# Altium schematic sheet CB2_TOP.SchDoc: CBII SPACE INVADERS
size A2; Engineer: SHOWELL; DocumentNumber: 1; Revision: 1.00; SheetNumber: 1; SheetTotal: 1; PageSetup: Record=PageOptions|CenterHorizontal=True|CenterVertical=True|PrintScale=1.47|XCorrection=1.00|YCorrection=1.00|PrintKind=0|BorderSize=5000000|LeftOffset=0|BottomOffset=0|Orientation=2|PaperLength=1000|PaperWidth=1000|Scale=100|PaperSource=7|PrintQuality=-4|MediaType=1|DitherType=10|PaperKind=A2|PrintScaleMode=1
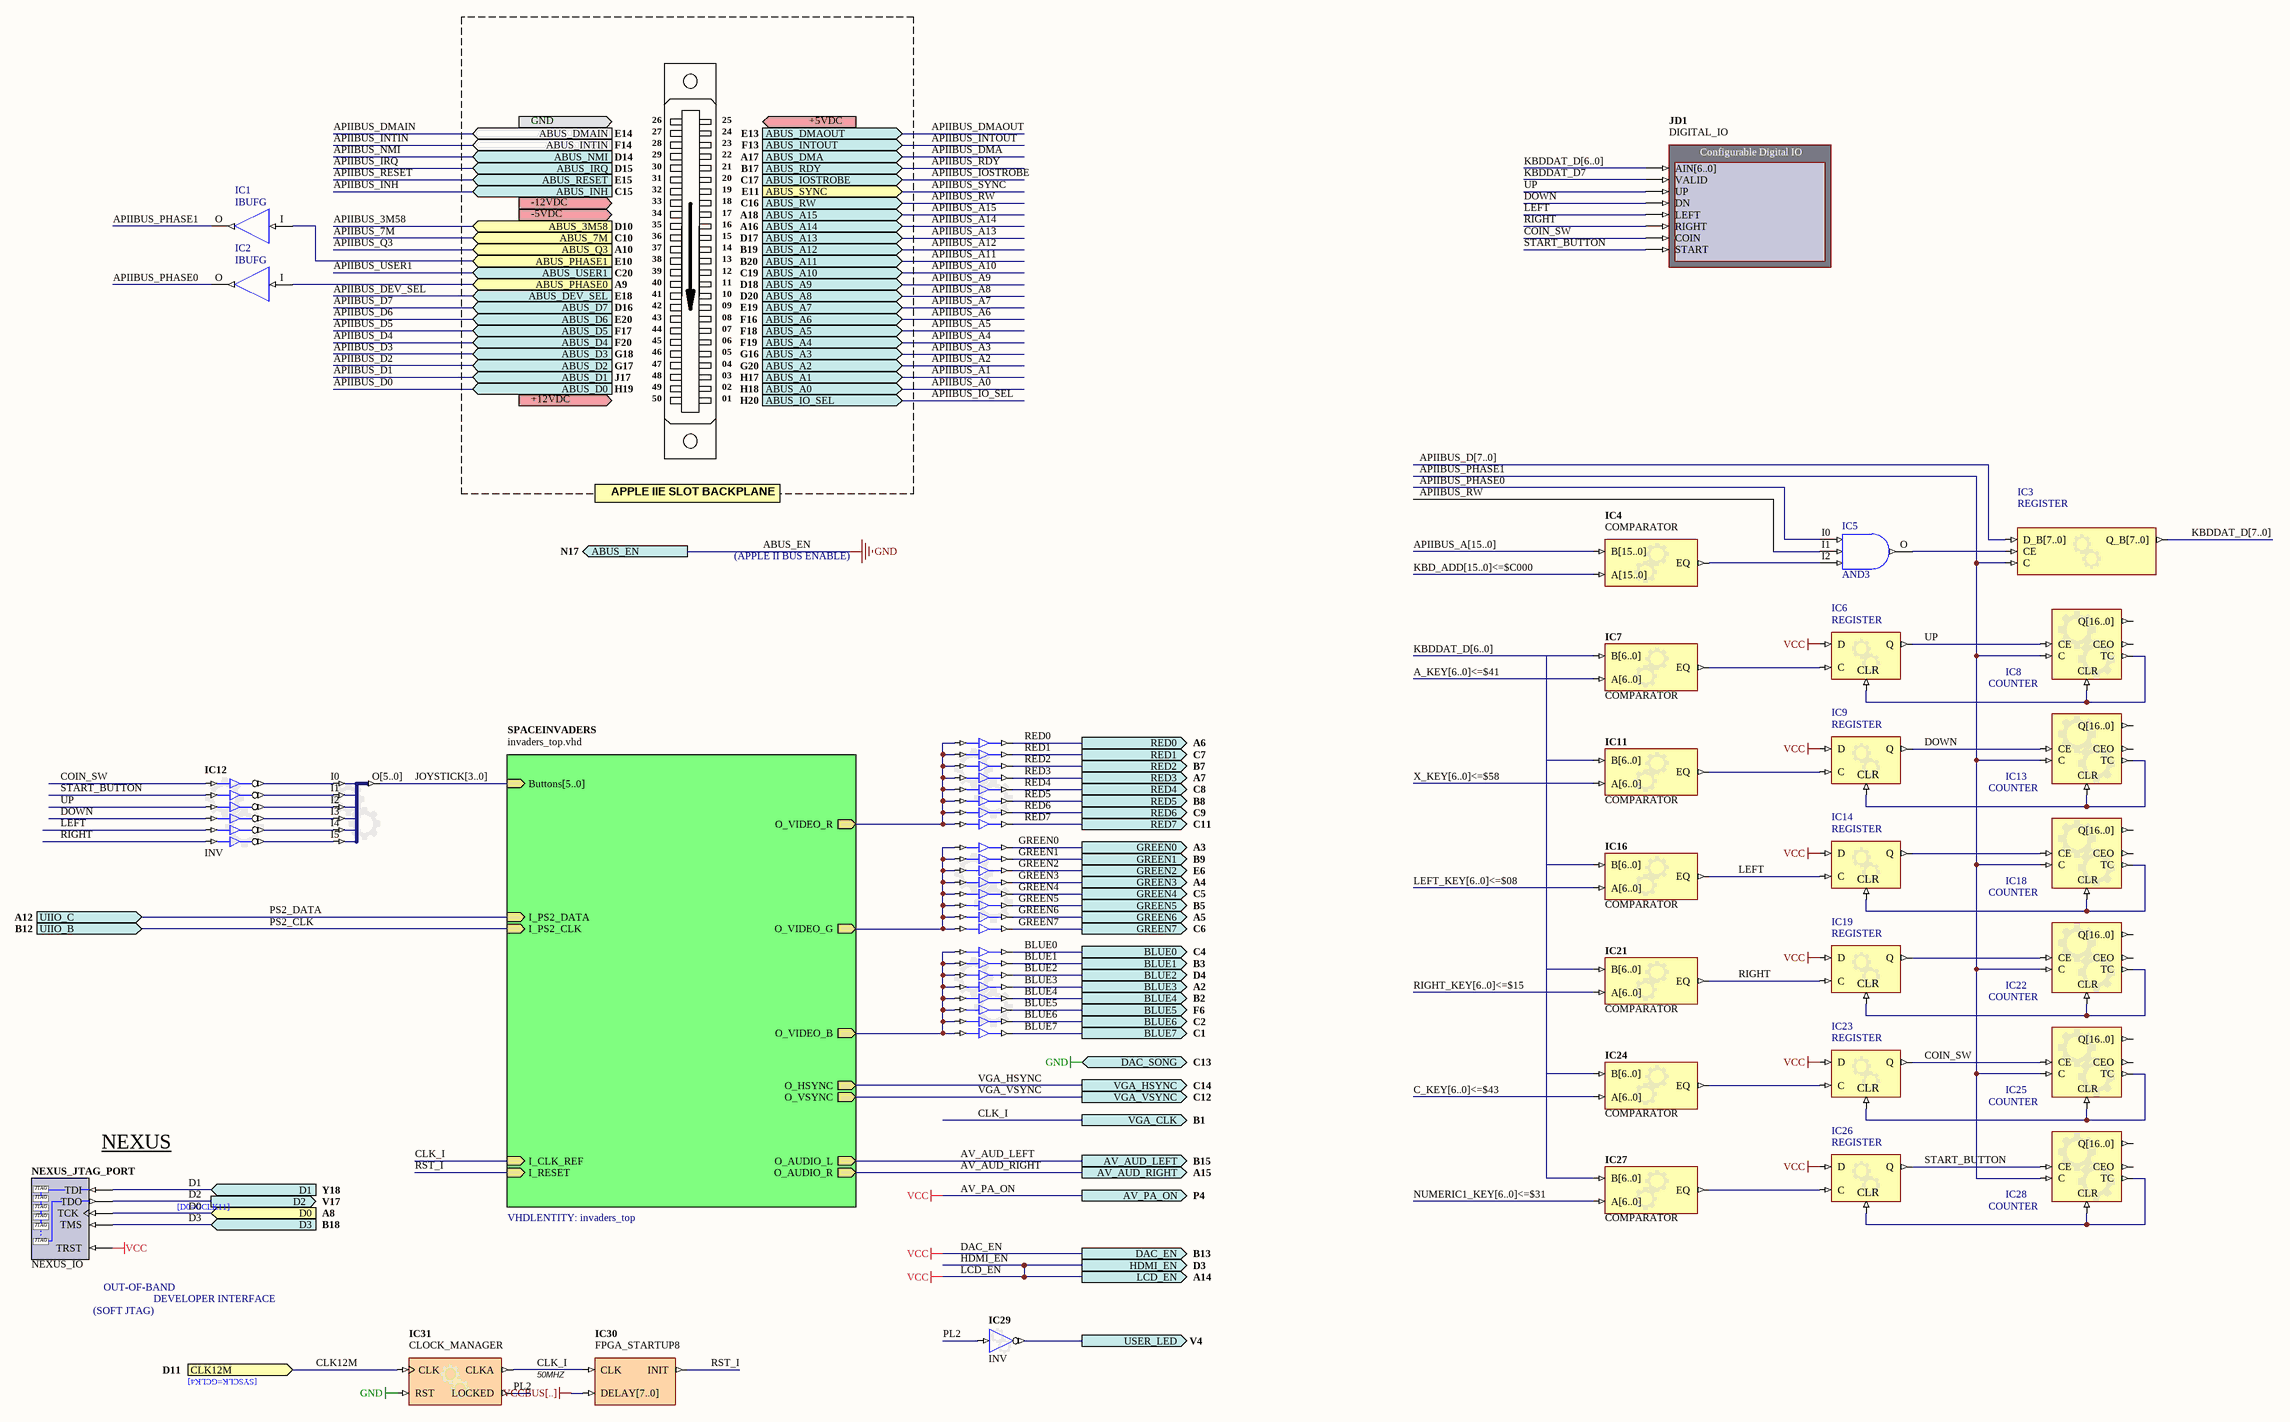
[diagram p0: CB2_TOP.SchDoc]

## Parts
IC1  IBUFG
IC2  IBUFG
IC3  REGISTER
IC4  COMPARATOR
IC5  AND3
IC6  REGISTER
IC7  COMPARATOR
IC8  COUNTER
IC9  REGISTER
IC10  BUF  (value not drawn)
IC11  COMPARATOR
IC12  INV
IC13  COUNTER
IC14  REGISTER
IC15  BUF  (value not drawn)
IC16  COMPARATOR
IC17  BUS_JS  (value not drawn)
IC18  COUNTER
IC19  REGISTER
IC20  BUF  (value not drawn)
IC21  COMPARATOR
IC22  COUNTER
IC23  REGISTER
IC24  COMPARATOR
IC25  COUNTER
IC26  REGISTER
IC27  COMPARATOR
IC28  COUNTER
IC29  INV
IC30  FPGA_STARTUP8
IC31  CLOCK_MANAGER
JD1  DIGITAL_IO
NEXUS_JTAG_PORT  NEXUS_IO

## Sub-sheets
SPACEINVADERS = invaders_top.vhd: I_CLK_REF (in), I_PS2_CLK (in), I_PS2_DATA (in), I_RESET (in), O_AUDIO_L (out), O_AUDIO_R (out), O_HSYNC (out), O_VIDEO_B (out), O_VIDEO_G (out), O_VIDEO_R (out), O_VSYNC (out), Buttons[5..0] (in)  | VHDLENTITY: invaders_top

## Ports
ABUS_3M58 (in, see D10), ABUS_7M (in, see C10), ABUS_A0 (in, see H18), ABUS_A1 (in, see H17), ABUS_A2 (in, see G20), ABUS_A3 (in, see G16), ABUS_A4 (in, see F19), ABUS_A5 (in, see F18), ABUS_A6 (in, see F16), ABUS_A7 (in, see E19), ABUS_A8 (in, see D20), ABUS_A9 (in, see D18), ABUS_A10 (in, see C19), ABUS_A11 (in, see B20), ABUS_A12 (in, see B19), ABUS_A13 (in, see D17), ABUS_A14 (in, see A16), ABUS_A15 (in, see A18), ABUS_D0 (in, see H19), ABUS_D1 (in, see J17), ABUS_D2 (in, see G17), ABUS_D3 (in, see G18), ABUS_D4 (in, see F20), ABUS_D5 (in, see F17), ABUS_D6 (in, see E20), ABUS_D7 (in, see D16), ABUS_DEV_SEL (in, see E18), ABUS_DMA (in, see A17), ABUS_DMAIN (in, see E14), ABUS_DMAOUT (in, see E13), ABUS_EN (out, see N17), ABUS_INH (in, see C15), ABUS_INTIN (in, see F14), ABUS_INTOUT (in, see F13), ABUS_IO_SEL (in, see H20), ABUS_IOSTROBE (in, see C17), ABUS_IRQ (in, see D15), ABUS_NMI (in, see D14), ABUS_PHASE0 (in, see A9), ABUS_PHASE1 (in, see E10), ABUS_Q3 (in, see A10), ABUS_RDY (in, see B17), ABUS_RESET (in, see E15), ABUS_RW (in, see C16), ABUS_SYNC (in, see E11), ABUS_USER1 (in, see C20), AV_AUD_LEFT (out, see B15), AV_AUD_RIGHT (out, see A15), AV_PA_ON (out, see P4), BLUE0 (out, see C4), BLUE1 (out, see B3), BLUE2 (out, see D4), BLUE3 (out, see A2), BLUE4 (out, see B2), BLUE5 (out, see F6), BLUE6 (out, see C2), BLUE7 (out, see C1), CLK12M (in, see D11), D0 (in, see A8), D1 (in, see Y18), D2 (out, see V17), D3 (in, see B18), DAC_EN (out, see B13), DAC_SONG (out, see C13), GREEN0 (out, see A3), GREEN1 (out, see B9), GREEN2 (out, see E6), GREEN3 (out, see A4), GREEN4 (out, see C5), GREEN5 (out, see B5), GREEN6 (out, see A5), GREEN7 (out, see C6), HDMI_EN (out, see D3), LCD_EN (out, see A14), RED0 (out, see A6), RED1 (out, see C7), RED2 (out, see B7), RED3 (out, see A7), RED4 (out, see C8), RED5 (out, see B8), RED6 (out, see C9), RED7 (out, see C11), UIIO_B (in, see B12), UIIO_C (in, see A12), USER_LED (out, see V4), VGA_CLK (out, see B1), VGA_HSYNC (out, see C14), VGA_VSYNC (out, see C12)

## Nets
ABUS_EN: IC31.RST ; port DAC_SONG, port ABUS_EN  [also labelled GND]
AV_PA_ON: IC6.D IC9.D IC14.D IC19.D IC23.D IC26.D NEXUS_JTAG_PORT.TRST ; port HDMI_EN, port AV_PA_ON, port DAC_EN, port LCD_EN  [also labelled DAC_EN, HDMI_EN, LCD_EN, VCC]
ABUS_PHASE0: IC2.I ; port ABUS_PHASE0
ABUS_PHASE1: IC1.I ; port ABUS_PHASE1
APIIBUS_PHASE0: IC2.O IC5.I0
APIIBUS_PHASE1: IC1.O IC3.C IC8.C IC13.C IC18.C IC22.C IC25.C IC28.C
APIIBUS_RW: IC5.I1 ; port ABUS_RW
AV_AUD_LEFT: port AV_AUD_LEFT, sheet SPACEINVADERS/O_AUDIO_L
AV_AUD_RIGHT: port AV_AUD_RIGHT, sheet SPACEINVADERS/O_AUDIO_R
BLUE0: IC20.O0 ; port BLUE0
BLUE1: IC20.O1 ; port BLUE1
BLUE2: IC20.O2 ; port BLUE2
BLUE3: IC20.O3 ; port BLUE3
BLUE4: IC20.O4 ; port BLUE4
BLUE5: IC20.O5 ; port BLUE5
BLUE6: IC20.O6 ; port BLUE6
BLUE7: IC20.O7 ; port BLUE7
CLK12M: IC31.CLK ; port CLK12M
CLK_I: IC30.CLK IC31.CLKA ; port VGA_CLK, sheet SPACEINVADERS/I_CLK_REF
COIN_SW: IC12.I0 IC23.Q IC25.CE JD1.COIN
D0: NEXUS_JTAG_PORT.TCK ; port D0
D1: NEXUS_JTAG_PORT.TDI ; port D1
D2: NEXUS_JTAG_PORT.TDO ; port D2
D3: NEXUS_JTAG_PORT.TMS ; port D3
DOWN: IC9.Q IC12.I3 IC13.CE JD1.DN
GREEN0: IC15.O0 ; port GREEN0
GREEN1: IC15.O1 ; port GREEN1
GREEN2: IC15.O2 ; port GREEN2
GREEN3: IC15.O3 ; port GREEN3
GREEN4: IC15.O4 ; port GREEN4
GREEN5: IC15.O5 ; port GREEN5
GREEN6: IC15.O6 ; port GREEN6
GREEN7: IC15.O7 ; port GREEN7
KBDDAT_D7: JD1.VALID
LEFT: IC12.I4 IC14.C IC16.EQ JD1.LEFT
PL2: IC29.I IC31.LOCKED
PS2_CLK: port UIIO_B, sheet SPACEINVADERS/I_PS2_CLK
PS2_DATA: port UIIO_C, sheet SPACEINVADERS/I_PS2_DATA
RED0: IC10.O0 ; port RED0
RED1: IC10.O1 ; port RED1
RED2: IC10.O2 ; port RED2
RED3: IC10.O3 ; port RED3
RED4: IC10.O4 ; port RED4
RED5: IC10.O5 ; port RED5
RED6: IC10.O6 ; port RED6
RED7: IC10.O7 ; port RED7
RIGHT: IC12.I5 IC19.C IC21.EQ JD1.RIGHT
RST_I: IC30.INIT ; sheet SPACEINVADERS/I_RESET
START_BUTTON: IC12.I1 IC26.Q IC28.CE JD1.START
UP: IC6.Q IC8.CE IC12.I2 JD1.UP
USER_LED: IC29.O ; port USER_LED
VGA_HSYNC: port VGA_HSYNC, sheet SPACEINVADERS/O_HSYNC
VGA_VSYNC: port VGA_VSYNC, sheet SPACEINVADERS/O_VSYNC
NetIC3_CE: IC3.CE IC5.O
NetIC4_EQ: IC4.EQ IC5.I2
NetIC6_C: IC6.C IC7.EQ
NetIC6_CLR: IC6.CLR IC8.CLR IC8.TC
NetIC9_C: IC9.C IC11.EQ
NetIC9_CLR: IC9.CLR IC13.CLR IC13.TC
NetIC10_I0: IC10.I0 IC10.I1 IC10.I2 IC10.I3 IC10.I4 IC10.I5 IC10.I6 IC10.I7 ; sheet SPACEINVADERS/O_VIDEO_R
NetIC12_O0: IC12.O0 IC17.I0
NetIC12_O1: IC12.O1 IC17.I1
NetIC12_O2: IC12.O2 IC17.I2
NetIC12_O3: IC12.O3 IC17.I3
NetIC12_O4: IC12.O4 IC17.I4
NetIC12_O5: IC12.O5 IC17.I5
NetIC14_CLR: IC14.CLR IC18.CLR IC18.TC
NetIC14_Q: IC14.Q IC18.CE
NetIC15_I0: IC15.I0 IC15.I1 IC15.I2 IC15.I3 IC15.I4 IC15.I5 IC15.I6 IC15.I7 ; sheet SPACEINVADERS/O_VIDEO_G
NetIC19_CLR: IC19.CLR IC22.CLR IC22.TC
NetIC19_Q: IC19.Q IC22.CE
NetIC20_I0: IC20.I0 IC20.I1 IC20.I2 IC20.I3 IC20.I4 IC20.I5 IC20.I6 IC20.I7 ; sheet SPACEINVADERS/O_VIDEO_B
NetIC23_C: IC23.C IC24.EQ
NetIC23_CLR: IC23.CLR IC25.CLR IC25.TC
NetIC26_C: IC26.C IC27.EQ
NetIC26_CLR: IC26.CLR IC28.CLR IC28.TC

Not connected (* = marked no-connect by the designer): IC3 D_B[7..0] Q_B[7..0]; IC4 A[15..0] B[15..0]; IC7 A[6..0] B[6..0]; IC8 CEO Q[16..0]; IC11 A[6..0] B[6..0]; IC13 CEO Q[16..0]; IC16 A[6..0] B[6..0]; IC17 O[5..0]; IC18 CEO Q[16..0]; IC21 A[6..0] B[6..0]; IC22 CEO Q[16..0]; IC24 A[6..0] B[6..0]; IC25 CEO Q[16..0]; IC27 A[6..0] B[6..0]; IC28 CEO Q[16..0]; IC30 DELAY[7..0]; JD1 AIN[6..0]

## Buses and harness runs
bus A_KEY[6..0]<=$41
bus APIIBUS_A[15..0]
bus APIIBUS_D[7..0]
bus C_KEY[6..0]<=$43
bus JOYSTICK[3..0] = sheet SPACEINVADERS/Buttons[5..0]
bus KBD_ADD[15..0]<=$C000
bus KBDDAT_D[6..0]
bus KBDDAT_D[7..0]
bus LEFT_KEY[6..0]<=$08
bus NUMERIC1_KEY[6..0]<=$31
bus RIGHT_KEY[6..0]<=$15
bus X_KEY[6..0]<=$58

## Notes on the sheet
- GND
- 26
- 27
- 28
- 29
- 30
- 25
- 24
- 23
- 22
- 21
- +5VDC
- -12VDC
- -5VDC
- 31
- 32
- 33
- 34
- 35
- 20
- 19
- 18
- 17
- 16
- 36
- 37
- 38
- 39
- 40
- 15
- 14
- 13
- 12
- 11
- 41
- 42
- 43
- 44
- 45
- 10
- 09
- 08
- 07
- 06
- +12VDC
- 46
- 47
- 48
- 49
- 50
- 05
- 04
- 03
- 02
- 01
- APPLE IIE SLOT BACKPLANE
- (APPLE II BUS ENABLE)
- (near NEXUS_JTAG_PORT) NEXUS
- (near NEXUS_JTAG_PORT) [D0=GCLK11]
- (SOFT JTAG)
- (near NEXUS_JTAG_PORT) OUT-OF-BAND
- DEVELOPER INTERFACE
- [SYSCLK=GCLK4]
- 50MHZ
- Labels drawn without touching a wire or pin: VCCBUS[..]

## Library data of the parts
IC1 IC2 = IBUFG: Dedicated Input Buffer using the LVTTL standard; FPGAVendor: Xilinx
IC3 = REGISTER: Configurable Register; ConfiguratorName: GENERIC_REGISTER; ConfigurationParameters: {}Version[1.1]{}RegisterType[DFlipFlop]{}NegativeTrigger[False]{}TriggerEnable[True]{}ResetMode[None]{}SetMode[None]{}SignalCount[1]{}SignalWidth0[8]{}OutputOption0[Normal]{}
IC4 = COMPARATOR: Configurable Comparator; ConfiguratorName: GENERIC_COMPARATOR; ConfigurationParameters: {}Version[1.0]{}EQ[True]{}GT[False]{}LT[False]{}SignalWidth[16]{}BusInputs[True]{}RegisterOutputs[False]{}NegClockEdge[False]{}
IC5 = AND3: 3-Input AND Gate; FPGAVendor: Xilinx
IC6 IC9 IC14 IC19 IC23 IC26 = REGISTER: Configurable Register; ConfiguratorName: GENERIC_REGISTER; ConfigurationParameters: {}Version[1.1]{}RegisterType[DFlipFlop]{}NegativeTrigger[False]{}TriggerEnable[False]{}ResetMode[Asynchronous]{}SetMode[None]{}SignalCount[1]{}SignalWidth0[1]{}OutputOption0[Normal]{}
IC7 IC11 IC16 IC21 IC24 IC27 = COMPARATOR: Configurable Comparator; ConfiguratorName: GENERIC_COMPARATOR; ConfigurationParameters: {}Version[1.0]{}EQ[True]{}GT[False]{}LT[False]{}SignalWidth[7]{}BusInputs[True]{}RegisterOutputs[False]{}NegClockEdge[False]{}
IC8 IC13 IC18 IC22 IC25 IC28 = COUNTER: Configurable Counter; ConfiguratorName: GENERIC_COUNTER; ConfigurationParameters: {}Version[1.0]{}Type[Binary]{}SyncReset[False]{}NegativeClockEdge[False]{}FixedDirection[True]{}IsIncrement[True]{}SignalWidth[17]{}MaxValue[100000]{}BusOutput[True]{}Loadable[False]{}BusInput[False]{}
IC10 IC15 IC20 = BUF: Configurable Buffer; ConfiguratorName: GENERIC_BUFFER; ConfigurationParameters: {}Version[1.1]{}SignalCount[8]{}SignalWidth0[1]{}OutputOption0[Normal]{}SignalWidth1[1]{}OutputOption1[Normal]{}SignalWidth2[1]{}OutputOption2[Normal]{}SignalWidth3[1]{}OutputOption3[Normal]{}SignalWidth4[1]{}OutputOption4[Normal]{}SignalWidth5[1]{}OutputOption5[Normal]{}SignalWidth6[1]{}OutputOption6[Normal]{}SignalWidth7[1]{}OutputOption7[Normal]{}EnableMode[None]{}ShowPinNames[False]{}
IC12 = INV: Configurable Inverter; ConfiguratorName: GENERIC_BUFFER; ConfigurationParameters: {}Version[1.1]{}SignalCount[6]{}SignalWidth0[1]{}OutputOption0[Inverted]{}SignalWidth1[1]{}OutputOption1[Inverted]{}SignalWidth2[1]{}OutputOption2[Inverted]{}SignalWidth3[1]{}OutputOption3[Inverted]{}SignalWidth4[1]{}OutputOption4[Inverted]{}SignalWidth5[1]{}OutputOption5[Inverted]{}EnableMode[None]{}ShowPinNames[False]{}
IC17 = BUS_JS: Configurable Bus Joiner/Splitter; ConfiguratorName: GENERIC_BUS_JS; ConfigurationParameters: {}Version[1.1]{}SplitterJoinerType[Joiner]{}SignalCount[6]{}SignalWidth0[1]{}GapBelow0[1000000]{}ConnectionType0[Pin]{}SignalWidth1[1]{}GapBelow1[1000000]{}ConnectionType1[Pin]{}SignalWidth2[1]{}GapBelow2[1000000]{}ConnectionType2[Pin]{}SignalWidth3[1]{}GapBelow3[1000000]{}ConnectionType3[Pin]{}SignalWidth4[1]{}GapBelow4[1000000]{}ConnectionType4[Pin]{}SignalWidth5[1]{}GapBelow5[1000000]{}ConnectionType5[Pin]{}ShowPinNames[True]{}
IC29 = INV: Configurable Inverter; ConfiguratorName: GENERIC_BUFFER; ConfigurationParameters: {}Version[1.1]{}SignalCount[1]{}SignalWidth0[1]{}OutputOption0[Inverted]{}EnableMode[None]{}ShowPinNames[False]{}
IC30 = FPGA_STARTUP8: FPGA Startup With 8 Bit Delay
IC31 = CLOCKMANAGER: Configurable Clock Manager; ConfiguratorName: GENERIC_CLOCKMANAGER; ConfigurationParameters: {}Version[1.0]{}Option_Configuration[object _1: TClockManagerPersist / VersionMajor [ 0 / VersionMinor [ 0 / InputFreq [ 24.000000000000000000 / InputName [ 'CLK' / OutputTargets [ < / item / Name [ 'CLKA' / OutFreqMin [ 100.000000000000000000 / OutFreqMax [ 100.000000000000000000 / OutPostDivider [ 1.000000000000000000 / end> / OutputDevices [ < / item / Name [ 'Spartan3AN' / Valid [ True / OutputActuals [ < / item / Name [ 'CLK0' / Multipler [ 1.000000000000000000 / Divider [ 1.000000000000000000 / OutFreq [ 24.000000000000000000 / OutputMap [ 1 / end / item / Name [ 'CLK90' / Multipler [ 1.000000000000000000 / Divider [ 1.000000000000000000 / OutPhase [ 90.000000000000000000 / OutFreq [ 24.000000000000000000 / OutputMap [ 2 / end / item / Name [ 'CLK180' / Multipler [ 1.000000000000000000 / Divider [ 1.000000000000000000 / OutPhase [ 180.000000000000000000 / OutFreq [ 24.000000000000000000 / OutputMap [ 3 / end / item / Name [ 'CLK270' / Multipler [ 1.000000000000000000 / Divider [ 1.000000000000000000 / OutPhase [ 270.000000000000000000 / OutFreq [ 24.000000000000000000 / OutputMap [ 4 / end / item / Name [ 'CLK2X' / Multipler [ 2.000000000000000000 / Divider [ 1.000000000000000000 / OutFreq [ 48.000000000000000000 / OutputMap [ 5 / end / item / Name [ 'CLKDV' / Multipler [ 1.000000000000000000 / Divider [ 16.000000000000000000 / OutFreq [ 1.500000000000000000 / OutputMap [ 6 / end / item / Name [ 'CLK2X180' / Multipler [ 1.000000000000000000 / Divider [ 1.000000000000000000 / OutPhase [ 180.000000000000000000 / OutFreq [ 48.000000000000000000 / OutputMap [ 7 / end / item / Name [ 'CLKFX' / Multipler [ 25.000000000000000000 / Divider [ 6.000000000000000000 / OutFreq [ 100.000000000000000000 / OutputMap [ 0 / end / item / Name [ 'CLKFX180' / Multipler [ 1.000000000000000000 / Divider [ 1.000000000000000000 / OutPhase [ 180.000000000000000000 / OutFreq [ 100.000000000000000000 / OutputMap [ 8 / end> / InternalActuals [ <> / CustomVars [ <> / end> / MinInputFreq [ 1.000000000000000000 / MaxInputFreq [ 280.000000000000000000 / MinOutputFreq [ 18.000000000000000000 / MaxOutputFreq [ 210.000000000000000000 / MaxOutputCount [ 9 / end]{}
JD1 = DIGITAL_IO: Configurable Digital IO; NEXUS_CORE: Instrument; NEXUS_JTAG_DEVICE: True; NEXUS_JTAG_ORDER: 0; ConfigurationParameters: {}Version[2.0]{}StorageType[3]{}InterfaceType[Parallel]{}SchCompWidth[140]{}Input0Name[AIN{1}6..0{2}]{}Input0Width[7]{}Input0InitValue[0]{}Input0Kind[Numeric]{}Input0NumRadix[Decimal]{}Input1Name[VALID]{}Input1Width[1]{}Input1InitValue[0]{}Input1Kind[LEDs]{}Input1LEDStyle[Green]{}Input2Name[UP]{}Input2Width[1]{}Input2InitValue[0]{}Input2Kind[LEDs]{}Input2LEDStyle[Red]{}Input3Name[DN]{}Input3Width[1]{}Input3InitValue[0]{}Input3Kind[LEDs]{}Input3LEDStyle[Red]{}Input4Name[LEFT]{}Input4Width[1]{}Input4InitValue[0]{}Input4Kind[LEDs]{}Input4LEDStyle[Red]{}Input5Name[RIGHT]{}Input5Width[1]{}Input5InitValue[0]{}Input5Kind[LEDs]{}Input5LEDStyle[Red]{}Input6Name[COIN]{}Input6Width[1]{}Input6InitValue[0]{}Input6Kind[LEDs]{}Input6LEDStyle[Red]{}Input7Name[START]{}Input7Width[1]{}Input7InitValue[0]{}Input7Kind[LEDs]{}Input7LEDStyle[Red]{}NoOutputs[ ]{}Designator[JD]{}InternalID[0]{}
NEXUS_JTAG_PORT = NEXUS_JTAG_PORT: Soft Nexus-Chain Connector; NEXUS_JTAG_CONNECTOR: True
